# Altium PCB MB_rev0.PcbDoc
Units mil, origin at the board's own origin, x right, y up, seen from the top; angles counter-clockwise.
Board outline 9750 x 2000 mil, 2 copper layers (Top Layer, Bottom Layer); 81 components, 58 nets, 289 pads, 92 vias.
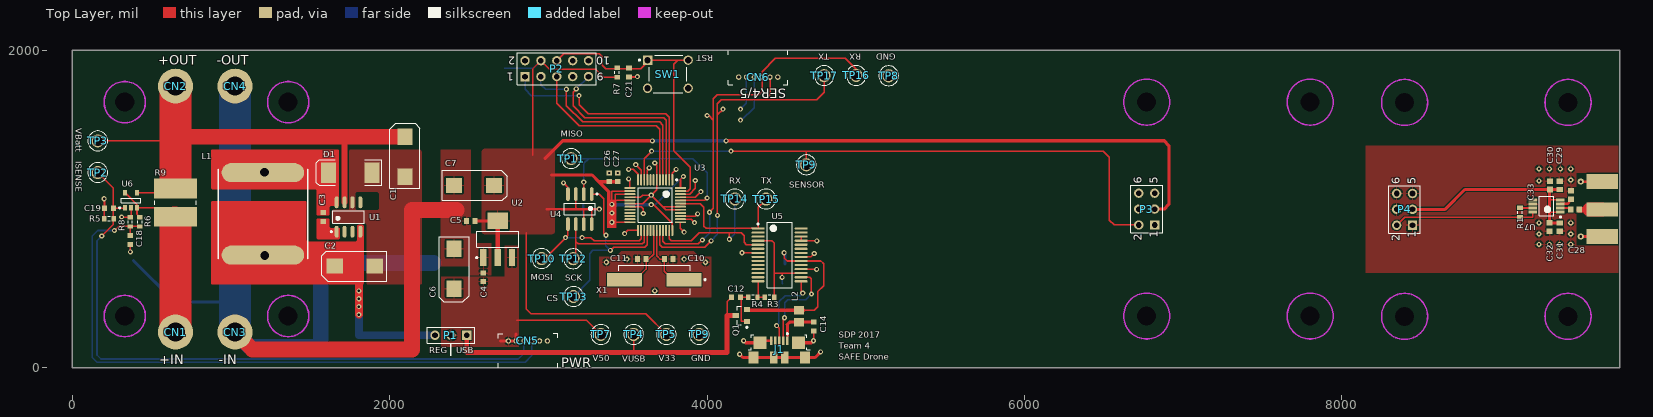
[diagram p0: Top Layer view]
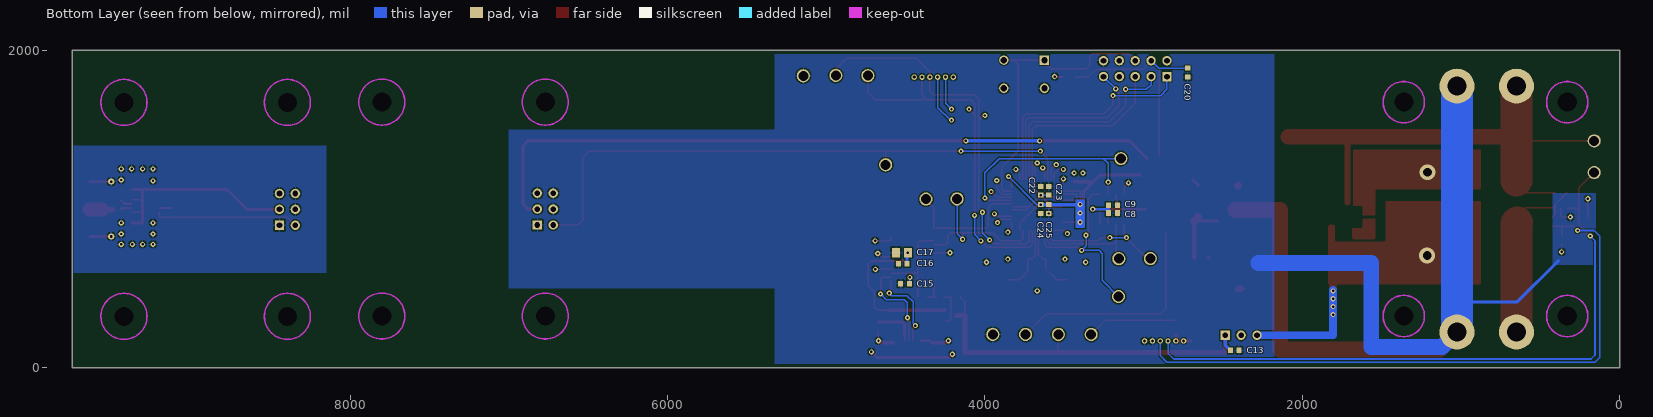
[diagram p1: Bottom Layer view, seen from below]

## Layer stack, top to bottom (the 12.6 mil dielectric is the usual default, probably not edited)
Top Solder: solder mask 0.4, Solder Resist, Dk 3.5
Top Layer: signal copper 1.4
Dielectric 1: dielectric 12.6, FR-4, Dk 4.8
Bottom Layer: signal copper 1.4
Bottom Solder: solder mask 0.4, Solder Resist, Dk 3.5

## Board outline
0,0 9750,0 9750,2000 0,2000

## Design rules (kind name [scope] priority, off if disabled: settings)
Clearance [All] p1: gap=8 ignorepadtopadclearanceinfootprint=TRUE except(0: Arc-Hole Track-Hole SMDPad-Hole THPad-Hole Via-Hole Fill-Hole Poly-Hole Region-Hole Text-Hole; 7: Arc-SMDPad Track-SMDPad SMDPad-SMDPad)
HoleSize [All] p1: absolutevalues=TRUE maxlimit=200 minlimit=15 maxpercent=80.000 minpercent=20.000
MinimumSolderMaskSliver [All] p1: minsoldermaskwidth=2.5
NetAntennae [All] p1 off: netantennaetolerance=20
PolygonConnect PolygonConnect_1 [(InComponent('U1') OR InComponent('C1') OR InComponent('C2') OR InComponent('D1'))] p1: connectstyle=Direct reliefconductorwidth=10 reliefentries=4 polygonreliefangle="90 Angle" airgapwidth=0
PolygonConnect [All] p2: connectstyle=Relief reliefconductorwidth=10 reliefentries=4 polygonreliefangle="90 Angle" airgapwidth=10
RoutingVias [All] p1: holewidth=15 width=32 viastyle="Through Hole" minholewidth=15 minwidth=32 maxholewidth=60 maxwidth=100
SilkToSilkClearance [All] p1 off: silktosilkclearance=6
SilkToSolderMaskClearance [IsPad] p1 off: minsilkscreentomaskgap=10 clearancetoexposedcopper=TRUE
SolderMaskExpansion [All] p1: expansion=4
Width [All] p1: maxlimit=300 minlimit=8 preferedwidth=8 minimp=50.000000 maximp=50.000000 favimp=50.000000
25 further rules are at their usual default settings.

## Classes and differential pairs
component class PSU: C1 C2 C3 C4 C5 C6 C7 C18 C19 CN1 CN2 CN3 CN4 D1 L1 P1 R5 R6 R8 R9 TP2 TP3 TP4 TP5 TP7 TP8 TP9 U1 U2 U6
component class COMS: C12 C13 C14 C15 C16 C17 J1 L2 Q1 R3 R4 RX TP14 TP15 U5
component class MCU: C8 C9 C10 C11 C20 C21 C22 C23 C24 C25 C26 C27 P2 R7 SW1 TP9 TP10 TP11 TP12 TP13 U3 U4 X1
component class WIRE: CN5 CN6 P3 TP16 TP17
component class SENS: C28 C29 C30 C31 C32 C33 P4 R1 U7

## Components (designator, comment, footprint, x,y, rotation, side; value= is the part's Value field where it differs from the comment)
C1 "15uF 25V" AVX-CAPC7343_V 2095,1330 r270 top
C2 "100uF 10V" AVX-CAPC7343_V 1780,640 r0 top
C3 "Cap Semi" 1608[0603] 1580,950 r270 top value=0.01uF
C4 "Cap Semi" 1608[0603] 2590,570 r270 top value=TBD
C5 "Cap Semi" 1608[0603] 2510,925 r0 top value=TBD
C6 "15uF 25V" AVX-CAPC7343_V 2405.28,624.09 r90 top
C7 "15uF 25V" AVX-CAPC7343_V 2530,1150 r180 top
C8 "Cap Semi" 1608[0603] 3192.56,975 r0 bottom value=0.01uF
C9 "Cap Semi" 1608[0603] 3192.56,1025 r180 bottom value=1uF
C10 "Cap Semi" 1608[0603] 3757.56,685 r180 top value=32pF
C11 "Cap Semi" 1608[0603] 3587.56,685 r0 top value=32pF
C12 "Cap Semi" 1608[0603] 4182.56,445 r180 top value=0.1uF
C13 "Cap Semi" 1608[0603] 2425,110 r0 bottom value=0.1uF
C14 "Cap Semi" 1608[0603] 4672.56,260 r90 top value=10nF
C15 "Cap Semi" 1608[0603] 4502.56,530 r0 bottom value=100nF
C16 "Cap Semi" 1608[0603] 4517.56,655 r180 bottom value=100nF
C17 "0805" 2012[0805] 4522.56,725 r180 bottom value=4.7uF
C18 "Cap Semi" 1608[0603] 365,805 r270 top value=100nF
C19 "Cap Semi" 1608[0603] 230,1005 r180 top value=100nF
C20 "Cap Semi" 1608[0603] 2722.56,1860 r90 bottom value=100nF
C21 "Cap Semi" 1608[0603] 3507.56,1860 r90 top value=100nF
C22 "Cap Semi" 1608[0603] 3647.56,1115 r90 bottom value=470pF
C23 "" 1608[0603] 3597.56,1115 r270 bottom value=2.2uF
C24 "Cap Semi" 1608[0603] 3647.56,1000 r270 bottom value=1nF
C25 "" 1608[0603] 3597.56,1000 r90 bottom value=4.7uF
C26 "Cap Semi" 1608[0603] 3382.56,1200 r90 top value=10nF
C27 "Cap Semi" 1608[0603] 3437.56,1200 r90 top value=1uF
C28 "680pF 0603" "CAP 680pF 0603" 9468.43,997 r180 top
C29 "100pF 0603" "Surface mnt capacitor" 9372,1149.38 r90 top
C30 "0.1uF 0603" "Surface mnt Cap" 9312,1149.57 r270 top
C31 "100pF 0603" "Surface mnt capacitor" 9373,886.62 r90 top
C32 "0.1uF 0603" "Surface mnt Cap" 9308,886.43 r90 top
C33 "680pF 0603" "CAP 680pF 0603" 9445,1088 r270 top
CN1 "+IN" WireConn_120mil 650,225 r0 top
CN2 "+OUT" WireConn_120mil 650,1775 r0 top
CN3 "-IN" WireConn_120mil 1025,225 r0 top
CN4 "-OUT" WireConn_120mil 1025,1775 r0 top
CN5 "PWR" CONN_PICOBLADE_6P 2747.15,35.14 r0 top
CN6 "SER4/5" CONN_PICOBLADE_6P 4445,1965 r180 top
D1 "Diode_SMC" SMC 1750,1230 r180 top
J1 "Micro-B USB" HIRO-ZX62R-B-5P_V 4454.09,117.66 r0 top locked
L1 "PE-53823SNL" IND_TOROID_SMT_PULSE 1200,970 r270 top
L2 "Ferrite" INDC2013X105X50ML20T30 4577.56,325 r90 top
P1 "Header 3" HDR1X3 2485,205 r180 top
P2 "JTAG" HDR2X5 2852.56,1835 r0 top
P3 "Header 3X2" HDR2X3 6820,900 r90 top locked
P4 "Header 3X2" HDR2X3 8445,898 r90 top locked
Q1 "IRLML6402G" INTR-SOT-23-3_V 4215,330 r90 top
R1 "Res3" J1-0603 9122,978 r270 top value=0R
R3 "Res3" J1-0603 4392.56,445 r0 top value=1K
R4 "Res3" J1-0603 4287.56,445 r180 top value=1K
R5 "Res3" J1-0603 230,940 r180 top value=49.9k
R6 "Res3" J1-0603 425,920 r270 top value=14k
R7 "Res3" J1-0603 3432.56,1860 r270 top value=10k
R8 "Res3" J1-0603 365,920 r90 top value=1.5k
R9 "CSS2725FTL500CT-ND" STAC-CSS2725-099H_V 650,1040 r90 top
SW1 "B3F-1000" OMRON-B3F-1000-4_V 3752.56,1850 r0 top locked
TP2 "ISENSE" KSTN-5011_V 160,1230 r0 top
TP3 "VBatt" KSTN-5011_V 160,1430 r0 top
TP4 "VUSB" KSTN-5011_V 3536.67,210 r0 top
TP5 "V33" KSTN-5011_V 3743.33,210 r0 top
TP7 "V50" KSTN-5011_V 3330,210 r0 top
TP8 "GND" KSTN-5011_V 5144,1840 r0 top
TP9 "SENSOR" KSTN-5011_V 4625,1279 r0 top
TP9 "GND" KSTN-5011_V 3950,210 r0 top
TP10 "MOSI" KSTN-5011_V 2957,688 r0 top
TP11 "MISO" KSTN-5011_V 3143,1318 r0 top
TP12 "SCK" KSTN-5011_V 3156,687 r0 top
TP13 "CS" KSTN-5011_V 3158,449 r0 top
TP14 "RX" KSTN-5011_V 4175,1064 r0 top
TP15 "TX" KSTN-5011_V 4371,1063 r0 top
TP16 "RX" KSTN-5011_V 4939,1842 r0 top
TP17 "TX" KSTN-5011_V 4737,1841 r0 top
U1 "LM2675MX-5.0" M08A_L 1740,950 r90 top
U2 "LM1117IMPX-3.3" MP04A_M 2680,810 r90 top
U3 "AT32UC3B1256-AUT" TQFP48_N 3672.56,1025 r270 top locked
U4 "8K EEPROM" SOIC-SN8_N 3197.56,1000 r270 top locked
U5 "FT232RL" SSOP-28_N 4456.73,711.34 r0 top locked
U6 "INA169" SOT23-5BL 370,1055 r90 top
U7 "MAX2015" TSOP65P490X110-8N 9026.8,1134.77 r180 top
X1 "ABLS2-32.000MHZ-D4YF-T" ABRA-ABLS2-2_V 3667.56,555 r180 top

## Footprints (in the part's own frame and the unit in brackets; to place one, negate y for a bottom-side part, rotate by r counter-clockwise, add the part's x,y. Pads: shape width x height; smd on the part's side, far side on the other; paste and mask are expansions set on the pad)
1608[0603] [mm] "Chip Capacitor, Body 1.6x0.8mm, IPC High Density"
  rect 0.8x0.9 smd: 1(-0.7,0) 2(0.7,0)
  body extent -0.87,-0.48 0.87,0.48, height 1.3
2012[0805] [mm] "Chip Resistor; Body 2.0 x 1.3 mm (LxW typ)"
  rect 1.3x1.5 smd: 1(-0.95,0) 2(0.95,0)
ABRA-ABLS2-2_V [mm] "SMD, 2-Leads, Body 11.4x4.7mm, Height 3.3mm"
  rect 5.6x2.1 smd: 1(-4.75,0) 2(4.75,0)
  silkscreen extent -8.23,-2.35 5.7,2.35, body extent -5.7,-2.35 5.7,2.35, height 3.3
AVX-CAPC7343_V [mm] "SMT Capacitor, 2 Leads, Body 7.3x4.3mm"
  rect 2.6x2.4 smd: 1(-3.202,0.007) 2(3.198,0.007)
  silkscreen extent -5.33,-2.4 5.08,2.4, body extent -3.49,-2.03 3.51,2.04, height 2.9
"CAP 680pF 0603" [mm] "Chip Capacitor, 2-Leads, Body 1.60x0.80mm, IPC Medium Density"
  rect 0.85x0.95 smd: 1(-0.675,0) 2(0.675,0)
  body extent -0.85,-0.45 0.85,0.45, height 0.9
CONN_PICOBLADE_6P [mm]
  round 0.864 hole 0.5: 1(0,3.4) 2(1.25,3.4) 3(2.5,3.4) 4(3.75,3.4) 5(5,3.4) 6(6.25,3.4)
  silkscreen extent -1.63,-0.86 7.9,4.6, body extent -1.5,-1.05 7.75,4.45, height 3.5
HDR1X3 [mm] "Connector; Header; 3 Position"
  rect 1.5x1.5 hole 0.9: 1(0,0)
  round 1.5 hole 0.9: 2(2.54,0) 3(5.08,0)
  silkscreen extent -1.27,-1.27 6.35,1.27
HDR2X3 [mm] "Connector; Header; 3x2 Position"
  rect 1.5x1.5 hole 0.9: 1(0,0)
  round 1.5 hole 0.9: 2(0,2.54) 3(2.54,0) 4(2.54,2.54) 5(5.08,0) 6(5.08,2.54)
  silkscreen extent -1.27,-1.27 6.35,3.81
HDR2X5 [mm] "Connector; Header; 5x2 Position"
  rect 1.5x1.5 hole 0.9: 1(0,0)
  round 1.5 hole 0.9: 2(0,2.54) 3(2.54,0) 4(2.54,2.54) 5(5.08,0) 6(5.08,2.54) 7(7.62,0) 8(7.62,2.54) 9(10.16,0) 10(10.16,2.54)
  silkscreen extent -1.27,-1.27 11.43,3.81
HIRO-ZX62R-B-5P_V [mm] "USB Micro-B R/A Connector"
  rect 0.4x1.35 smd: 1(1.3,1.338) 2(0.65,1.338) 3(0,1.338) 4(-0.65,1.338) 5(-1.3,1.338)
  rect 2.1x2 smd: 6(-3.1,1.012) 11(3.1,1.012)
  rect 1.6x1.9 smd: 7(-4.1,-1.338) 10(4.1,-1.338)
  rect 1.2x1.9 smd: 8(-0.85,-1.338) 9(0.85,-1.338)
  silkscreen extent -4.95,-0.13 4.95,2.58, body extent -4.4,-3.95 4.4,1.78, height 2.71
IND_TOROID_SMT_PULSE [mil] "LCI-37 PACKAGE"
  oval 120x520 smd: 1(-260,0) 2(260,0)
  silkscreen extent -282,-282 282,282, body extent -285,-285 285,285, height 360
INDC2013X105X50ML20T30 [mm] "Chip Inductor, 2-Leads, Body 2.2x1.45mm, IPC Low Density"
  rect 1.39x1.59 smd: 1(-0.955,0) 2(0.955,0)
  body extent -1.1,-0.72 1.1,0.72, height 1.05
INTR-SOT-23-3_V [mm] "SOT23, 3-Leads, Body 2.92x1.3mm, Pitch 1.9mm"
  rect 0.802x0.972 smd: 1(-0.95,-0.885) 2(0.95,-0.885) 3(0,0.885)
  silkscreen extent -2.03,-1.01 1.46,0.64, body extent -1.46,-0.65 1.46,0.65, height 1.12
J1-0603 [mm] "Chip Resistor, Body 1.6x0.8mm, IPC High Density"
  rect 0.7x0.9 smd: 1(-0.75,0) 2(0.75,0)
  silkscreen extent -0.2,-0.35 0.2,0.35, body extent -0.85,-0.48 0.85,0.48, height 0.9
KSTN-5011_V [mm] "Test Point, Dia 3.17mm"
  round 2.1 hole 1.6: 1(0,0)
  silkscreen extent -1.59,-1.58 1.59,1.58, body extent -1.59,-1.59 1.59,1.59, height 8.13
M08A_L [mm] "SOIC, 8-Leads, Body 4.9x3.9mm, Pitch 1.27mm, IPC High Density"
  oval 1.9x0.6 smd: 1(-2.35,1.905) 2(-2.35,0.635) 3(-2.35,-0.635) 4(-2.35,-1.905) 5(2.35,-1.905) 6(2.35,-0.635) 7(2.35,0.635) 8(2.35,1.905)
  silkscreen extent -2.47,-2.5 1,2.88, body extent -2,-2.5 2,2.5, height 1.75
MP04A_M [mm] "SOT223, 4-Leads, Body 6.5x3.5mm, Pitch 2.3mm, Lead Span 7mm, IPC Low Density"
  rect 2.7x1 smd: 1(-2.95,2.3) 2(-2.95,0) 3(-2.95,-2.3)
  rect 2.7x3.3 smd: 4(2.95,0)
  silkscreen extent -3.07,-3.35 1.3,3.47, body extent -1.86,-3.35 1.86,3.35, height 1.8
OMRON-B3F-1000-4_V [mm] "TH, 4-Leads, Body 6x6mm"
  rect 1.5x1.5 hole 1 paste+0: 1(-3.25,2.25)
  round 1.5 hole 1 paste+0: 2(3.25,2.25) 3(-3.25,-2.25) 4(3.25,-2.25)
  silkscreen extent -4.67,-3 3,3, body extent -3,-3 3,3, height 4.5
SMC [mm] "DO-214-AB/SMC; 2 C-Bend Leads; Body 7.9 x 5.9 mm, inc. leads (LxW)"
  rect 2.4x3.3 smd: 1(-3.475,0) 2(3.475,0)
  silkscreen extent -5.07,-2.05 5.43,2.05
SOIC-SN8_N [mm] "SOIC, 8-Leads, Body 4.9x3.9mm, Pitch 1.27mm, IPC Medium Density"
  oval 2.2x0.6 smd: 1(-2.4,1.905) 2(-2.4,0.635) 3(-2.4,-0.635) 4(-2.4,-1.905) 5(2.4,-1.905) 6(2.4,-0.635) 7(2.4,0.635) 8(2.4,1.905)
  silkscreen extent -2.52,-2.5 0.9,2.88, body extent -2,-2.5 2,2.5, height 1.75
SOT23-5BL [mm] "SOT23, 5-Leads, Body 2.9x1.6mm, Pitch 0.95mm, Lead Span 2.8mm, IPC High Density"
  rect 0.9x0.65 smd: 1(-1.2,0.95) 2(-1.2,0) 3(-1.2,-0.95) 4(1.2,-0.95) 5(1.2,0.95)
  silkscreen extent -1.32,-1.55 0.35,1.95, body extent -0.9,-1.55 0.9,1.55, height 1.19
SSOP-28_N [mm] "SOP, 28-Leads, Body 10.2x5.3mm, Pitch 0.65mm, IPC Medium Density"
  oval 2.1x0.35 smd: 1(-3.45,4.225) 2(-3.45,3.575) 3(-3.45,2.925) 4(-3.45,2.275) 5(-3.45,1.625) 6(-3.45,0.975) 7(-3.45,0.325) 8(-3.45,-0.325) 9(-3.45,-0.975) 10(-3.45,-1.625) 11(-3.45,-2.275) 12(-3.45,-2.925) 13(-3.45,-3.575) 14(-3.45,-4.225) 15(3.45,-4.225) 16(3.45,-3.575) 17(3.45,-2.925) 18(3.45,-2.275) 19(3.45,-1.625) 20(3.45,-0.975) 21(3.45,-0.325) 22(3.45,0.325) 23(3.45,0.975) 24(3.45,1.625) 25(3.45,2.275) 26(3.45,2.925) 27(3.45,3.575) 28(3.45,4.225)
  silkscreen extent -3.57,-5.25 2,5.25, body extent -2.8,-5.25 2.8,5.25, height 2
STAC-CSS2725-099H_V [mm] "Chip Resistor, 2-Leads, Body 7.06x6.7mm"
  rect 3.18x6.86 smd: 1(-2.25,0) 2(2.25,0)
  silkscreen extent -0.3,-3.33 0.3,3.33, body extent -3.53,-3.35 3.53,3.35, height 1.24
"Surface mnt Cap" [mm] "0.1uF 0603"
  rect 0.9x1 smd: 1(-0.675,0) 2(0.675,0)
  body extent -0.87,-0.48 0.87,0.47, height 0.87
"Surface mnt capacitor" [mm] "100pF 0603"
  rect 0.84x1.02 smd: 1(-0.67,0) 2(0.67,0)
  body extent -0.89,-0.51 0.88,0.5, height 0.91
TQFP48_N [mm] "Thin QFP, 48-Leads, Body 7x7mm, Pitch 0.5mm, IPC Medium Density"
  oval 1.8x0.3 smd: 1(-4.05,2.75) 2(-4.05,2.25) 3(-4.05,1.75) 4(-4.05,1.25) 5(-4.05,0.75) 6(-4.05,0.25) 7(-4.05,-0.25) 8(-4.05,-0.75) 9(-4.05,-1.25) 10(-4.05,-1.75) 11(-4.05,-2.25) 12(-4.05,-2.75) 25(4.05,-2.75) 26(4.05,-2.25) 27(4.05,-1.75) 28(4.05,-1.25) 29(4.05,-0.75) 30(4.05,-0.25) 31(4.05,0.25) 32(4.05,0.75) 33(4.05,1.25) 34(4.05,1.75) 35(4.05,2.25) 36(4.05,2.75)
  oval 0.3x1.8 smd: 13(-2.75,-4.05) 14(-2.25,-4.05) 15(-1.75,-4.05) 16(-1.25,-4.05) 17(-0.75,-4.05) 18(-0.25,-4.05) 19(0.25,-4.05) 20(0.75,-4.05) 21(1.25,-4.05) 22(1.75,-4.05) 23(2.25,-4.05) 24(2.75,-4.05) 37(2.75,4.05) 38(2.25,4.05) 39(1.75,4.05) 40(1.25,4.05) 41(0.75,4.05) 42(0.25,4.05) 43(-0.25,4.05) 44(-0.75,4.05) 45(-1.25,4.05) 46(-1.75,4.05) 47(-2.25,4.05) 48(-2.75,4.05)
  silkscreen extent -4.17,-2.75 2.75,3.58, body extent -3.5,-3.5 3.5,3.5, height 1.2
TSOP65P490X110-8N [mm] "TSOP, 8-Leads, Body 3.00x3.00mm, Pitch 0.65mm, IPC Medium Density"
  rect 1.35x0.5 smd: 1(-8.9,3.9) 2(-8.9,3.25) 3(-8.9,2.6) 4(-8.9,1.95) 5(-4.45,1.95) 6(-4.45,2.6) 7(-4.45,3.25) 8(-4.45,3.9)
  silkscreen extent -9.02,1.37 -5.52,4.82, body extent -9.13,1.37 -4.22,4.47, height 1.1
WireConn_120mil [mil]
  round 220 hole 120: 1(0,0)

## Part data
C1 C6 C7: library part CMP-0279-00002-2, "15µF ±10% Molded Tantalum Capacitors 25V 2312 (6032 Metric) 100 mOhm", Capacitance=15uF, Manufacturer=AVX, PartNumber=TPSD156K025S0100, Rated Voltage=25V, Tolerance=10%
C2: library part CMP-0279-00002-2, "15µF ±10% Molded Tantalum Capacitors 10V 2312 (6032 Metric) 50 mOhm", Capacitance=100uF, Manufacturer=AVX, PartNumber=TPSD156K025S0100, Rated Voltage=10V, Tolerance=10%
C3 C4 C5 C8 C9 C10 C11 C12 C13 C14 C15 C16 C18 C19 C20 C21: "Capacitor (Semiconductor SIM Model)"
C17: library part "Cap SMT", "Capacitor (Semiconductor SIM Model)"
C22 C24 C26 C27: "Capacitor (Semiconductor SIM Model)", Tempco=NP0
C23 C25: library part "Cap SMT", "Capacitor (Semiconductor SIM Model)", Tempco=X7R
C28 C33: library part "Surface Mount Cap", "Surface Mount Capacitor"
C29 C31: library part "Surface mnt cap 100pF"
CN1 CN2 CN3 CN4: library part Wire_Conn_Batt
CN5 CN6: library part CONN_PicoBlade_6P_RA, "PicoBlade right angle through hole conn", Insulation Color=Natural, Manufacturer="Molex, LLC", Manufacturer Part Number=0530480610, Supplier Part Number 1=WM1746-ND
D1: "DO-214-AB / SMC SCHOTTKY"
J1: library part CMP-0031-00001-1, "Connector; USBMicro-B,Reverse type, SMT; 5 Position; Right Angle", Operating Temperature="-30 to 85 degC", PartNumber=ZX62R-B-5P(30)
L1: "FIXED IND 38UH 1.2A 100 MOHM SMD", Current - Saturation=-, Current Rating=1.2A, DC Resistance (DCR)="100 mOhm", Inductance=38µH, Manufacturer="Pulse Electronics Corporation", Operating Temperature="-40°C ~ 130°C", Package / Case=Nonstandard, Supplier Part Number 1=33uH
L2: library part CMP-1660-00003-1, "Chip Inductor, 21 Ohm, +/- 30%, 6 A, -40 to 125 degC, 0805 (2012 Metric), RoHS, Tape and Reel", Case\Package=0805, Case Code (Metric)=2012, Current Rating="6 A", Max Operating Temperature="125 degC", Min Operating Temperature="-40 degC", Package Quantity=1, Resistance="4 mohm", Tolerance=30%
P1: "Header, 3-Pin"
P2: library part "Header 5X2", "Header, 5-Pin, Dual row"
P3 P4: "Header, 3-Pin, Dual row"
Q1: library part CMP-0676-00001-1, "HEXFET Power MOSFET, P-Channel, -20 V VDSS, 0.065 Ohm RDS, 3-Pin SOT23, RoHS, Tape and Reel", Manufacturer="International Rectifier", PartNumber=IRLML6402GPbF
R1 R3 R4 R7: "Resistor"
R5 R6 R8: "Resistor", Tempco=25ppm
R9: library part CMP-1719-00001-2, "Chip Resistor, 0.5 mOhm, +/- 1%, 4 W, -55 to 225 degC, 2725 (6865 Metric), RoHS, Tape and Reel", Max Operating Temperature="225 degC", Min Operating Temperature="-55 degC", Package Quantity=1000, Resistance="0.5 mOhm", Tolerance=1%
SW1: library part CMP-1677-00002-1, "Tactile Switch, SPST-NO, 0.05 A, 5 to 24 V, -25 to 70 degC, 4-Pin THD, RoHS, Bulk", Capacitance="-45 f", Current Rating="1.5 A", Max Operating Temperature="70 degC", Min Operating Temperature="-40 degC", Package Quantity=1080, Voltage Rating="150 V"
TP2 TP3 TP4 TP5 TP7 TP8 TP9 TP9 TP10 TP11 TP12 TP13 TP14 TP15 TP16 TP17: library part CMP-1672-00003-4, "Test Point, Black, Through Hole, RoHS, Bulk", Colour=Black, Manufacturer=Keystone, Package Quantity=100
U1: library part CMP-0069-00673-2, "SIMPLE SWITCHER® Power Converter High Efficiency 1A Step-Down Voltage Regulator, 8-pin Narrow SOIC", Manufacturer="National Semiconductor", PackageTopMarking=NSZXTT*2675*M5.0, PowerWise=N
U2: library part CMP-0062-01630-3, "800mA Low-Dropout Linear Regulator, 4-pin SOT-223", Manufacturer="National Semiconductor", PackageTopMarking=XYTT*N05B, PowerWise=N
U3: "32-bit AVR UC3 B Series Microcontroller, 256KB Flash, 32KB SRAM, 28 GPIO pins, Industrial Grade, 48-Pin TQFP, Tray", Supplier Part Number 1=AT32UC3B1256-AUT-ND
U4: library part CMP-0165-00135-1, "8K SPI Bus Serial EEPROM, 8-Pin SOIC, Tape and Reel", Manufacture PN=CAT25080VI-GT3
U5: library part CMP-0078-00028-3, "USB UART Asynchronous Serial Data Transfer Chip, 28-pin SSOP, Tube", Manufacturer=FTDI, PartNumber=FT232RL-Tube
U6: Current - Output=-, Manufacturer="Texas Instruments", Manufacturer Part Number=INA169NA/250, Operating Temperature="-40°C ~ 85°C", Package / Case="SC-74A, SOT-753", Supplier Device Package=SOT-23-5, Voltage - Input="2.7 V ~ 60 V"
U7: "IC"
X1: library part CMP-0277-00002-1, "Low Profile Surface Mount Microprocessor Crystal, 4.096 MHz +/-30 ppm, 180 Ohm, -40 to 85 degC, 2-Pin 11.4 x 4.7 x 3.3 mm SMD, RoHS, Tape and Reel", Freq. Stability="+/- 30 ppm", Frequency="32.0 MHz", Load Capacitance="18 pF", Manufacturer=Abracon, Operating Temp. Range="-40 to 85 degC", Shunt Capacitance="7 pF Max."

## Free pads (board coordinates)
  rect 200x95 smd: 1(9640,827.5) 1(9640,1172.5)
  rect 200x90 smd: 1(9640,997)
  round 0 hole 120: 3(330.1,326) 3(330.1,1674) 3(1360.1,326) 3(1360.1,1674) 3(6770,326) 3(6770,1674) 3(7800,326) 3(7800,1674) 3(8395,324) 3(8395,1672) 3(9425,324) 3(9425,1672)

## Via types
v1: diameter 32, hole 15, Top Layer to Bottom Layer, 88 vias
v2: diameter 38, hole 18, Top Layer to Bottom Layer, 2 vias
v3: diameter 100, hole 55, Top Layer to Bottom Layer, 2 vias

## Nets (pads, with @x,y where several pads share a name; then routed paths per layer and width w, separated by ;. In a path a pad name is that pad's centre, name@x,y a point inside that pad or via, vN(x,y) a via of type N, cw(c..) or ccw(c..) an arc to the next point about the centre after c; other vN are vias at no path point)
AIN_SENSOR: P3.2 TP9.1@4625,1279 U3.10 | length 3781.8
  Top Layer w8: U3.10 3603.66,1318.66 v1(3650,1365) ; v1(4150,1365) 4630,1365 ; TP9.1@4625,1279 4625,1360 4630,1365 ; P3.2 6565,900 6535,930 6535,1325 6495,1365 4630,1365
  Bottom Layer w8: v1(3650,1365) v1(4150,1365)
CS: TP13.1 U3.28 U4.1 | length 1220.4
  Top Layer w8: U4.1 3320,1094.49 3350,1064.49 3350,847.56 v1(3362.56,835) ; v1(3390,740) 3410,760 3607.56,760 3623.35,775.79 U3.28
  Bottom Layer w8: TP13.1 3260,551 3260,720 3280,740 v1(3390,740) 3362.56,767.44 v1(3362.56,835)
DM: U3.39 | length 113.7
  Top Layer w8: U3.39 3926.1,956.1 v1(3940,970)
DP: U3.38 | length 96.9
  Top Layer w8: U3.38 3898.58,936.42 v1(3920,915)
GND: C1.2 C2.2 C4.1 C5.1 C6.2 C7.2 C8.1 C9.2 C10.1 C11.1 C13.1 C14.1 C15.2 C16.1 C17.1 C18.2 C19.2 C20.1 C21.1 C22.2 C23.1 C24.2 C25.1 C26.2 C27.2 C29.2 C30.1 C31.1 C32.1 C33.1 CN3.1 CN4.1 CN5.5 CN5.6 CN6.6 D1.1 J1.5 J1.6 J1.7 J1.8 J1.9 J1.10 J1.11 P2.2 P2.10 P3.1 P3.4 P3.5 P3.6 P4.1 P4.4 P4.5 P4.6 pad.1@9640,827.5 pad.1@9640,1172.5 R5.2 R8.2 SW1.3 SW1.4 TP8.1 TP9.1@3950,210 U1.6 U2.1 U3.1 U3.13 U3.19 U3.37 U4.4 U5.7 U5.18 U5.21 U5.25 U5.26 U6.2 U7.5 U7.6 | length 8755.9
  Top Layer w8: v1(3095,1165) 3122.56,1137.44 U4.4 ; v1(3505,1190) 3513.11,1181.89 U3.13 ; U3.19 3584.84,1015.16 3597.56,1002.44 v1(3597.56,972.44) ; U3.1 3780.83,1225.83 v1(3805,1250) ; U3.37 3832.01,877.99 v1(3855,855)
  Top Layer w10: v1(200,1065) 202.44,1062.56 C19.2 200.47,1003.03 R5.2 ; v1(310,950) 310.47,949.53 R8.2 370,954.53 U6.2 ; v1(365,730) C18.2 ; C21.1 3557.44,1832.44 v1(3560,1835) ; v1(4220,725) 4220.87,724.13 U5.7 ; U5.18 4688.23,621.77 v1(4690,620) ; U5.21 4653.54,698.54 v1(4675,720) ; U5.26 U5.25 4690.91,800.91 v1(4691.81,800) ; v1(4670,170) 4672.56,172.56 C14.1
  Top Layer w15: J1.6 4344.84,170.32 J1.5
  Top Layer w18: v2(9505,827.5) pad.1@9640,827.5 ; v2(9505,1172.5) pad.1@9640,1172.5
  Top Layer w20: v1(4205,85) 4225,65 J1.7 J1.8 J1.9 J1.10 4680,65 v1(4715,100) ; v1(4230,170) 4242.48,157.52 J1.6 ; J1.11 4657.52,157.52 v1(4670,170)
  Top Layer w25: U2.1 U2.1@2590,693.86
  Top Layer w50: C7.2 C7.2@2405,1148.82
  Top Layer w100: CN3.1 1135,115 2140,115 2140,995 2420,995
  Bottom Layer w20: 385,675 645,415 1025,415
  Bottom Layer w100: CN3.1 1120,130 1565,130 1565,660 2275,660
  Bottom Layer w200: CN3.1 1025,415 CN4.1
  other v1: 3670,485 3365,665 3990,665 3495,685 3855,685 9242,778 9307,778 9372,778 9442,778 9242,843 9442,843 9242,913 9442,913 9242,1178 9442,1183 3382.56,1227.56 3437.56,1227.56 9242,1253 9307,1253 9377,1253 9442,1253
MISO: TP11.1 U3.44 U4.2 | length 1462.5
  Top Layer w8: U4.2 v1(3222.56,1170) ; U3.44 3984.53,1054.53 v1(4000,1070)
  Bottom Layer w8: TP11.1 3253,1318 ; v1(3222.56,1170) 3222.56,1287.56 3253,1318 ; v1(4000,1070) 4000,1227.56 3909.56,1318 3253,1318
MOSI: TP10.1 U3.26 U4.5 | length 845.5
  Top Layer w8: TP10.1 2975.56,688 v1(3107.56,820) 3122.56,835 U4.5 ; v1@3212.56,815 v1(3212.56,820) 3267.56,820 3287.56,800 3572.56,800 3583.98,811.42 U3.26
  Bottom Layer w8: v1(3107.56,820) v1(3212.56,820)
NetC3_1: C3.1 D1.2 L1.1 U1.8
  other v3: 1210,1232
NetC3_2: C3.2 U1.1
NetC10_2: C10.2 U3.31 X1.1 | length 440.1
  Top Layer w10: U3.31 3682.4,705.16 3702.56,685 C10.2 3730,607.56 3782.56,555 X1.1
NetC11_2: C11.2 U3.30 X1.2 | length 435.6
  Top Layer w10: X1.2 3547.56,555 3615.12,622.56 C11.2 3632.72,685 3662.72,715 U3.30
NetC12_1: C12.1 Q1.1 R4.2 | length 235.2
  Top Layer w8: C12.1 C12.1@4215,445 ; Q1.1 4215,292.6 C12.1@4215,445 ; R4.2 4248.03,445 C12.1@4215,445
NetC15_1: C15.1 R3.2 U5.4 U5.17 | length 687.6
  Top Layer w8: R3.2 R3.2@4422.56,445.47
  Top Layer w10: U5.4 4407.56,800.91 4422.56,785.91 4422.56,596.18 ; R3.2@4422.56,445.47 4422.56,596.18 ; v1(4472.56,570) 4472.56,596.18 ; U5.17 4472.56,596.18 ; 4422.56,596.18 4472.56,596.18
  Bottom Layer w10: v1(4472.56,570) 4472.56,530 C15.1
NetC16_2: C16.2 C17.2 L2.2 Q1.2 U5.20 | length 1146.9
  Top Layer w10: v1(4485.16,725) 4485.16,692.4 4504.61,672.95 U5.20 4717.05,672.95 4735,655 4735,517.44 4697.56,480 4697.56,385 4675.16,362.6 L2.2
  Top Layer w20: Q1.2 4254.65,362.6 4610,362.6
  Bottom Layer w20: v1(4485.16,725) 4490,720.16 C16.2
NetC18_1: C18.1 CN5.4 R6.2 R8.1 | length 4039.7
  Top Layer w10: v1(265,865) 290.47,890.47 R8.1 ; C18.1 R8.1 ; R6.2 R8.1
  Bottom Layer w10: v1(265,865) 160,865 125,830 125,65 155,35 2853,35 2894.79,76.79 CN5.4
NetC19_1: C19.1 CN5.3 R5.1 TP2.1 U6.1 | length 4103.2
  Top Layer w10: TP2.1 257.56,1132.44 C19.1 ; v1(185,830) 257.56,902.56 C19.1 ; U6.1 329.84,1005 C19.1
  Bottom Layer w10: v1(185,830) 155,800 155,80 180,55 2810,55 2845.57,90.57 CN5.3
NetC28_2: C28.2 U7.2 | length 74.5
  Top Layer w15: U7.2 9441.85,1006.82 C28.2
NetC33_2: C33.2 U7.3 | length 72.8
  Top Layer w15: U7.3 9422.26,1032.41 C33.2@9441.85,1052
NetCN1_1: CN1.1 R6.1 R9.1 U6.3 U6.5 | length 1183.3
  Top Layer w10: U6.5 407.4,1027.44 U6.3 ; R6.1 407.4,967.13 U6.3 ; R9.1@645,915 645,956.42 593.66,1007.76 U6.3
  Top Layer w200: R9.1@645,915 650,910 CN1.1
NetCN6_4: CN6.4 | length 310.7
  Bottom Layer w8: v1(4210,1560) 4215.79,1560 4295.79,1640 4295.79,1829.57 CN6.4
NetCN6_5: CN6.5 | length 216.9
  Bottom Layer w8: v1(4210,1630) 4246.57,1666.57 4246.57,1829.57 CN6.5
NetJ1_2: J1.2 U5.16 | length 600.1
  Top Layer w8: J1.2 4479.69,307.13 v1(4487.56,315) ; U5.16 4646.97,570.59 4657.56,560 v1(4657.56,465)
  Bottom Layer w8: v1(4487.56,315) 4487.56,410 4507.56,430 4622.56,430 v1(4657.56,465)
NetJ1_3: J1.3 U5.15 | length 509.7
  Top Layer w8: v1(4437.56,265) 4454.09,248.46 J1.3 ; U5.15 4592.56,480 v1(4602.56,470)
  Bottom Layer w8: v1(4437.56,265) 4452.56,280 4452.56,415 4492.56,455 4587.56,455 v1(4602.56,470)
NetR1_1: R1.1 U7.7 | length 80.3
  Top Layer w10: R1.1 9122.71,1006.82 U7.7
OUT: P4.2 R1.2 U7.8 | length 910.7
  Top Layer w10: P4.2 8395.48,948.48 9066.99,948.48 ; 9066.99,948.47 R1.2 9202,948.47 U7.8
PA03: U3.7
PA04: U3.8
PA05: U3.9 | length 80.4
  Top Layer w8: U3.9 3623.35,1243.35 3635,1255 v1(3635,1260)
PA07: U3.11 | length 109.6
  Top Layer w8: v1(3550,1280) 3583.98,1246.02 U3.11
PA08: U3.12 | length 107.7
  Top Layer w8: v1(3505,1250) 3535,1250 3564.29,1220.71 U3.12
PA09: U3.20
PA10: U3.21
PA11: U3.22
PA12: U3.23
PA13: U3.25 | length 92.8
  Top Layer w8: v1(3480,845) 3500,865 3563.74,865 U3.25
PA17: U3.29
PA22: U3.34
PA26: U3.45 | length 142.8
  Top Layer w8: U3.45 3924.21,1074.21 v1(3960,1110)
PA27: U3.46 | length 157.9
  Top Layer w8: U3.46 3888.9,1093.9 3925,1130 v1(3925,1180)
PWREN: R3.1 R4.1 U5.14 | length 161.7
  Top Layer w8: U5.14 4320.91,458.82 4307.09,445 R3.1
R\S\T\: C21.2 P2.6 R7.1 SW1.1 SW1.2 U3.47 | length 1877.3
  Top Layer w8: P2.6 3097.56,1980 3320,1980 3340,1960 3340,1905 3360,1885 3582.56,1885 3624.61,1927.05 SW1.1 3815,1938.58 ; U3.47 3878.58,1113.58 3892.56,1127.56 3892.56,1265 3790,1367.56 3790,1913.58 3815,1938.58 ; SW1.2 3815,1938.58
RF_IN: C28.1 pad.1@9640,997 | length 145
  Top Layer w35: C28.1 pad.1@9560,997
  Top Layer w90: pad.1@9560,997 pad.1@9640,997
RXD1: TP15.1 U3.43 U5.1 | length 828.8
  Top Layer w8: U3.43 3955.16,1034.84 3980,1010 3980,892.68 3995,877.68 U5.1 4320.91,1012.91 TP15.1
RXD2: CN6.2 TP17.1 U3.32 | length 2329.1
  Top Layer w8: U3.32 3702.09,775.47 3717.56,760 3985,760 v1(4025,800) ; v1(4065,960) 4065,1595 ; v1(4100,1630) 4065,1595 ; CN6.2 4394.21,1829.57 4397,1826.78 4397,1722 4365,1690 ; TP17.1 4737,1737 4690,1690 4365,1690 ; 4065,1595 4065,1665 4090,1690 4365,1690
  Bottom Layer w8: v1(4025,800) 4065,840 v1(4065,960)
SCK: TP12.1 U3.27 U4.6 | length 741.7
  Top Layer w8: TP12.1 3172.56,703.56 3172.56,795 ; U4.6 3172.56,795 ; U3.27 3603.66,791.1 3592.56,780 3187.56,780 3172.56,795
TCK: P2.1 U3.2 | length 1489.7
  Top Layer w8: v1(3192.56,1715) 3192.56,1657.44 3250,1600 3740,1600 3761.14,1578.86 U3.2
  Bottom Layer w8: P2.1 2852.56,1755 2892.56,1715 v1(3192.56,1715)
TDI: P2.9 U3.3 | length 1223.8
  Top Layer w8: v1(3175.06,1757.5) 3155,1737.44 3155,1650 3230,1575 3725,1575 3741.46,1558.54 U3.3
  Bottom Layer w8: v1(3175.06,1757.5) P2.9
TDO: P2.3 U3.4 | length 1329.4
  Top Layer w8: v1(3112.56,1755) 3112.56,1652.44 3215,1550 3700,1550 3721.77,1528.23 U3.4
  Bottom Layer w8: P2.3 2952.56,1785 2982.56,1755 v1(3112.56,1755)
TMS: P2.5 U3.5 | length 1217.2
  Top Layer w8: P2.5@3062.09,1825.47 P2.5 3052.56,1667.44 3195,1525 3680,1525 3702.09,1502.91 U3.5
TXD1: TP14.1 U3.35 U5.5 | length 1003.6
  Top Layer w8: U3.35 3761.14,811.42 3772.56,800 3900,800 3950,850 4140,850 ; v1(4140,810) 4140,850 ; U5.5 4247.24,775.32 4232.56,790 4232.56,832.44 4215,850 4140,850
  Bottom Layer w8: v1(4140,810) 4175,845 TP14.1
TXD2: CN6.3 TP16.1 U3.33 | length 2452.3
  Top Layer w8: U3.33 3721.77,795.79 3737.56,780 3945,780 v1(3970,805) ; v1(4000,1590) 4010,1590 4040,1560 ; v1(4015,980) 4040,1005 4040,1560 ; TP16.1 4939,1882 4871,1950 4430,1950 4346.57,1866.57 CN6.3 4346.57,1741.57 4325,1720 4065,1720 4040,1695 4040,1560
  Bottom Layer w8: v1(3970,805) 4015,850 v1(4015,980)
V18: C22.1 C23.2 U3.6 U3.16 U3.18 U3.41 U3.42 | length 903
  Top Layer w8: U3.18 3594.96,1034.84 v1(3647.56,1087.44) ; U3.16 3580,1074.21 3593.23,1087.44 v1(3647.56,1087.44) ; v1(3670,1290) 3682.4,1277.6 U3.6 3682.4,1122.28 v1(3647.56,1087.44) ; U3.41 3739.53,995.47 3719.84,1015.16 ; U3.42 3719.84,1015.16 ; v1(3647.56,1087.44) 3719.84,1015.16
  Bottom Layer w8: C23.2 v1(3647.56,1087.44)
V33: C5.2 C7.1 C8.2 C9.1 C20.2 C24.1 C25.2 C26.1 C27.1 C29.1 C30.2 C31.2 C32.2 P2.4 P3.3 P4.3 R7.2 TP5.1 U2.2 U2.4 U3.14 U3.15 U3.17 U3.24 U3.36 U3.48 U4.3 U4.7 U4.8 U7.1 U7.4 | length 11892.7
  Top Layer w8: U4.3 3172.56,1007.44 3180,1000 ; 3220,1000 3222.56,997.44 U4.7 ; 3270,1000 3272.56,997.44 U4.8 ; v1(3400,916.73) U3.24 ; 3400,1055 3400,1113.58 U3.14 ; U3.17 3420,1054.53 3420,1093.9 U3.15 ; v1(3647.56,1027.56) 3662.37,1027.56 3780.83,909.1 U3.36
  Top Layer w10: 2860,850 2860,370 2890,340 3613.33,340 TP5.1 ; 2900,1340 2900,1882.44 P2.4 3007.56,1880 3300,1880 3349.53,1830.47 R7.2 ; U3.48 3832.01,1187.01 v1(3850,1205) ; 9308,979 9308,981.23 U7.1 ; 9308,1057 9308,1058 U7.4
  Top Layer w15: 2990,1000 3180,1000 3220,1000 3270,1000 v1(3320,1000)
  Top Layer w20: C5.2 U2.4@2680,925 ; C7.1 C7.1@2691.34,1185 ; 2980,1320 3090,1430 v1(3655,1430) ; 3020,1215 3275,1215 3317.56,1172.44 ; 3410,1000 3380,1030 3380,1110 3317.56,1172.44 ; C27.1 C26.1 3317.56,1172.44 ; v1(4120,1430) 6880,1430 6910,1400 6910,1030 6880,1000 P3.3 ; P4.3 8650,998 8775,1123 C30.2@9308,1123 ; 9308,979 C32.2 C31.2 ; 9308,981.23 9308,1057 ; 9308,1058 C30.2@9308,1123 ; C29.1 C30.2 C30.2@9308,1123
  Top Layer w30: U2.2 U2.4@2680,925
  Top Layer w50: U2.4@2656.06,948.94 U2.4@2680,925
  Bottom Layer w8: C20.2 2905.12,1887.56 P2.4
  Bottom Layer w10: v1(3647.56,1027.56) 3672.56,1027.56 v1(3850,1205)
  Bottom Layer w15: C8.2 3220.12,1000 ; C9.1 3220.12,1000 ; v1(3320,1000) 3220.12,1000
  Bottom Layer w20: v1@3390,1027.56 C25.2 v1(3647.56,1027.56) ; v1(3655,1430) v1(4120,1430)
  other v1: 3400,975 3400,1030
V50: C4.2 C6.1 CN5.1 CN5.2 P1.2 TP7.1 U2.3 | length 728.6
  Top Layer w10: 2800,300 3240,300 TP7.1
  Top Layer w20: 2697,169 CN5.1 CN5.2 2796.36,211
  Top Layer w40: C6.1@2385,498.03 C6.1
VBatt: C1.1 CN2.1 R9.2 TP3.1 U1.7 U6.4 | length 3266.1
  Top Layer w10: TP3.1 630,1430 650,1410 ; U6.4 623.66,1102.24 645,1123.58 R9.2@645,1175
  Top Layer w40: U1.7 1715,1456.06
  Top Layer w100: 650,1495 ccw(c690,1495) 690,1455 cw(c691.06,1455) 691.06,1456.06 1715,1456.06 C1.1@2088,1456.06
  Top Layer w200: R9.2@650,1180 650,1410 650,1495 CN2.1
VBUS: C14.2 J1.1 L2.1 | length 276
  Top Layer w10: J1.1 4505.28,200 ; C14.2@4672.4,287.4 C14.2
  Top Layer w20: 4505.56,200 4505.56,272.43 4505.28,272.72 4519.96,287.4 L2.1 C14.2@4672.4,287.4
Vreg50: C2.1 L1.2 P1.3 U1.4 | length 1005
  Top Layer w50: v1(1805,335) v1(1805,385) v1(1805,435) v1(1805,485) 1805,575
  Bottom Layer w50: v1@1805,490 v1(1805,485) v1(1805,435) v1(1805,385) v1(1805,335) 1805,205 P1.3
  other v3: 1213,707
VUSB: C12.2 C13.2 P1.1 Q1.3 TP4.1 | length 2388.7
  Top Layer w10: TP4.1 3536.67,108.33 3540,105 ; 4125,330 4127.44,332.44 4127.44,417.44 C12.2 ; Q1.3 Q1.3@4187.44,322.72
  Top Layer w30: P1.1 2485,97 4125,97 4125,330 Q1.3
  Bottom Layer w20: C13.2 2485,142.44 P1.1
pads on no net: CN6.1 J1.4 P2.7 P2.8 U1.2 U1.3 U1.5 U3.40 U5.2 U5.3 U5.6 U5.8 U5.9 U5.10 U5.11 U5.12 U5.13 U5.19 U5.22 U5.23 U5.24 U5.27 U5.28

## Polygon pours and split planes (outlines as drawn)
V50 on Top Layer "V50" (solid, pour order 6): 2325,575 2725,575 2725,770 2814,770 2814,132 2325,132
V33 on Top Layer "Top Layer-No Net 1" (solid, pour order 10): 2580,1360 cw(c2600,1360) 2600,1380 3020,1380 cw(c3020,1360) 3040,1360 3040,860 cw(c3020,860) 3020,840 2600,840 cw(c2600,860) 2580,860
GND on Top Layer "Top Layer-No Net" (solid, pour order 4): 3320,445 3320,700 3425,700 3460,735 3915,735 3950,700 4025,700 4025,445
GND on Top Layer "Top Layer-No Net" (solid, pour order 2): 1635,985 cw(c1645,985) 1645,995 1735,995 ccw(c1735,1005) 1745,1005 1745,1365 cw(c1755,1365) 1755,1375 2185,1375 cw(c2185,1360) 2200,1360 2200,535 cw(c2192.48,532.51) 2195,525 1865,525 cw(c1865,535) 1855,535 1855,900 ccw(c1845,900) 1845,910 1645,910 cw(c1645,920) 1635,920
GND on Top Layer "Top Layer-No Net" (solid, pour order 8): 2505,640.71 2505,584 2640,584 2640,785 2545,785 2545,845 2510,845 2510,1375 2320,1375 2320,640.71
GND on Top Layer "Top Layer-No Net 1" (solid, remove dead copper, pour order 22): 8150.67,1400.04 8150.67,600.04 9740.67,600.04 9740.67,1400.04
GND on Bottom Layer "Top Layer-No Net 1" (solid, pour order 28): 2175,1975 5325,1975 5325,1500 7000,1500 7000,500 5325,500 5325,25 2175,25
GND on Bottom Layer "Top Layer-No Net 1" (solid, pour order 16): 150,1100 150,650 420,650 420,1100
GND on Bottom Layer "Top Layer-No Net 1" (solid, remove dead copper, pour order 30): 8150.67,1400.04 8150.67,600.04 9740.67,600.04 9740.67,1400.04

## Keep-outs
Keep-Out Layer:
  circle w10: c330.1,1674 r130
  circle w10: c1360.1,1674 r130
  circle w10: c330.1,326 r130
  circle w10: c1360.1,326 r130
  circle w10: c6770,1674 r145
  circle w10: c7800,1674 r145
  circle w10: c7800,326 r145
  circle w10: c6770,326 r145
  circle w10: c8395,324 r145
  circle w10: c9425,324 r145
  circle w10: c9425,1672 r145
  circle w10: c8395,1672 r145

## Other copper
Top Layer:
  rectangle net V33: 3370,880 3430,1060
  pour cut-out: 9476,1230 9476,770 9750,770 9750,1230
  region net NetC3_1: 875,1365 cw(c885,1365) 885,1375 1670,1375 cw(c1670,1365) 1680,1365 1680,1020 1630,1020 ccw(c1630,1010) 1620,1010 1620,970 cw(c1610,970) 1610,960 1550,960 cw(c1550,970) 1540,970 1540,1115 ccw(c1530,1115) 1530,1125 885,1125 cw(c885,1135) 875,1135
  region net Vreg50: 875,1040 cw(c885,1040) 885,1050 1465,1050 cw(c1465,1040) 1475,1040 1475,805 ccw(c1485,805) 1485,795 1780,795 ccw(c1782.5,807.5) 1795,805 1795,890 cw(c1805,890) 1805,900 1825,900 cw(c1825,890.01) 1835,890 1835,610 1835,592.94 1835,535 cw(c1825.79,534.21) 1825,525 1560,525 1450,525 885,525 cw(c885,535) 875,535
  region net NetC3_2: 1540,930 cw(c1550,930) 1550,940 1610,940 cw(c1610,930) 1620,930 1620,890 ccw(c1630,890) 1630,880 1685,880 1685,820 cw(c1675,820) 1675,810 1550,810 cw(c1550,820) 1540,820
  pour cut-out: 1796.84,995 cw(c1796.84,1005) 1786.84,1005 1786.84,1096.84 cw(c1795,1096.84) 1795,1105 1920,1105 cw(c1920,1095) 1930,1095 1930,1005 cw(c1920,1005) 1920,995
Bottom Layer:
  rectangle net V33: 3370,880 3430,1060

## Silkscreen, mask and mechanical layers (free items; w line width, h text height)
Top Overlay:
  lines w8: 2385,75 2385,155
  text "RST" at 4040,1970 h38 r180
  text "SDP 2017" at 4830,190 h38
  text "Team 4" at 4830,120 h38
  text "REG" at 2250,90 h38
  text "USB" at 2420,90 h38
  text "SAFE Drone" at 4830,50 h38
M1-Board Outline:
  lines w10: 0,0 0,2000 2400,2000 8125,2000 9750,2000 9750,0 8125,0 0,0
M3-PCB Notes for Self:
  circle w10: c330.1,328 r110
  circle w10: c1360.1,328 r110
  circle w10: c1360.1,1676 r110
  circle w10: c330.1,1676 r110
  circle w10: c6770,1672 r110
  circle w10: c7800,1672 r110
  circle w10: c7800,324 r110
  circle w10: c6770,324 r110
  circle w10: c8395,1672 r110
  circle w10: c9425,1672 r110
  circle w10: c9425,324 r110
  circle w10: c8395,324 r110
  lines w10: 1625,0 ccw(c-2310,1000) 1625,2000 ; 1675,2650 1675,3025 ; 1750,2775 1675,2850 ; 1750,2925 1675,2850 ; 2050,-925 1975,-850 ; 2050,-775 1975,-850 ; 2176.13,1999.59 ccw(c4916.5,1000.5) 2176.51,0.38 ; 3125,2850 1675,2850 ; 3425,-850 1975,-850 ; 4825,-850 6100,-850 ; 5225,2850 6500,2850 ; 5948.49,1999.62 cw(c3208.5,999.5) 5948.87,0.41 ; 6025,-925 6100,-850 ; 6025,-775 6100,-850 ; 6425,2775 6500,2850 ; 6425,2925 6500,2850 ; 6500,0 cw(c10435,1000) 6500,2000 ; 6500,2650 6500,3025 ; 7798,1595.1 7798.1,1595 ; 332,1753 ccw(c332,1676) 332.1,1599 1358.21,1599 ; 332,1753 332,1753 ; 332,1753 1358.1,1753 cw(c1358.21,1676) 1358.21,1599 ; 332.1,405 ccw(c332.1,328) 332.21,251 1358.31,251 ccw(c1358.31,328) 1358.21,405 332.1,405 ; 332.1,405 332.1,405 ; 1358.21,1599 1358.21,1599 ; 6771.9,1749 ccw(c6771.9,1672) 6772,1595 7798.1,1595 ; 6771.9,1749 6771.9,1749 ; 6771.9,1749 7798,1749 cw(c7798.1,1672) 7798.1,1595 ; 6772,401 ccw(c6772,324) 6772.1,247 7798.21,247 ; 6772,401 7798.1,401 cw(c7798.21,324) 7798.21,247 ; 6772,401 6772,401 ; 7798.21,247 7798.21,247 ; -40,3240 1960,3240 1960,3440 -40,3440 -40,3240 ; 0,75 75,0 8050,0 8125,75 8125,1925 8050,2000 75,2000 0,1925 0,75 ; 1353.1,251 1353.1,251 ; 8125,0 8125,2000 9750,2000 9750,0 8125,0
  text "NOT FOR FAB - MECH NOTES" at 0,3300 h80
  text "Region between top/bot boards" at 3325,2825 h60
  text "(POWER OUT TO FC)" at 2700,2200 h80
  text "(BATT EXIT)" at 450,2150 h80
  text "SUGG. DAUGHTERBOARD / SIZE: 1.625Wx2.000H" at 8150,2100 h80
  text "Hex standoff (0.290dia OD) x4 / #4-40 screw (0.220dia head) x4" at 9805,1580 h60
  text "Slots in bottom board" at 260,1040 h60
  text "Panhead / #4-40 (x8)" at 110,470 h60
  text "(CURR SENSING)" at 550,-450 h80
  text "(POWER SUPPLIES)" at 1700,-450 h80
  text "MICROCONTROLLER" at 3500,-450 h80
  text "(SERIAL TO FC)" at 3000,-600 h80
  text "(EEPROM?)" at 4400,-600 h80
  text "(BATT ENTER)" at 325,-625 h80
  text "HIGH DC CURRENT REGION" at 3475,-880 h60
Drill Drawing:
  circle w10: c105.62,3400.83 r33.33
  lines w10: 72.29,2467.5 105.62,2484.17 138.96,2467.5 122.29,2500.83 138.96,2534.17 105.62,2517.5 72.29,2534.17 88.96,2500.83 72.29,2467.5 ; 72.29,2684.17 138.96,2684.17 105.62,2617.5 72.29,2684.17 ; 72.29,2767.5 138.96,2767.5 138.96,2834.17 72.29,2834.17 72.29,2767.5 ; 72.29,2934.17 88.96,2934.17 88.96,2917.5 122.29,2917.5 122.29,2934.17 138.96,2934.17 138.96,2967.5 122.29,2967.5 122.29,2984.17 88.96,2984.17 88.96,2967.5 72.29,2967.5 72.29,2934.17 ; 72.29,3134.17 138.96,3134.17 105.62,3067.5 72.29,3134.17 ; 72.29,3234.17 88.96,3234.17 105.62,3217.5 122.29,3234.17 138.96,3234.17 122.29,3250.83 138.96,3267.5 122.29,3267.5 105.62,3284.17 88.96,3267.5 72.29,3267.5 88.96,3250.83 72.29,3234.17 ; 72.29,3517.5 138.96,3517.5 138.96,3584.17 72.29,3584.17 72.29,3517.5 ; 85.62,2670.83 125.62,2670.83 105.62,2630.83 85.62,2670.83 ; 85.62,3530.83 125.62,3530.83 125.62,3570.83 85.62,3570.83 85.62,3530.83
  lines w15: 12.5,2422.5 10593.57,2422.5 ; 12.5,3622.5 10593.57,3622.5 ; 563.38,2272.5 563.38,3772.5 ; 1153.22,2272.5 1153.22,3772.5 ; 2302.88,2272.5 2302.88,3772.5 ; 2808.76,2272.5 2808.76,3772.5 ; 3542.56,2272.5 3542.56,3772.5 ; 5042.11,2272.5 5042.11,3772.5 ; 5631.96,2272.5 5631.96,3772.5 ; 6377.76,2272.5 6377.76,3772.5 ; 7027.59,2272.5 7027.59,3772.5 ; 7881.35,2272.5 7881.35,3772.5 ; 9214.96,2272.5 9214.96,3772.5 ; 12.5,2272.5 10593.57,2272.5 10593.57,3772.5 12.5,3772.5 12.5,2272.5
  text "Symbol" at 102.5,3667.5 h72
  text "Count" at 608.38,3667.5 h72
  text "Hole Size" at 1198.22,3667.5 h72
  text "Plated" at 2347.88,3667.5 h72
  text "Hole Type" at 2853.76,3667.5 h72
  text "Drill Layer Pair" at 3587.56,3667.5 h72
  text "Via/Pad" at 5087.11,3667.5 h72
  text "Pad Shape" at 5676.96,3667.5 h72
  text "Template" at 6422.76,3667.5 h72
  text "Description" at 7072.59,3667.5 h72
  text "Hole Tolerance (+)" at 7926.35,3667.5 h72
  text "Hole Tolerance (-)" at 9259.96,3667.5 h72
  text "2" at 608.38,3517.5 h60
  text "18.00mil (0.457mm)" at 1198.22,3517.5 h60
  text "PTH" at 2347.88,3517.5 h60
  text "Round" at 2853.76,3517.5 h60
  text "Top Layer - Bottom Layer" at 3587.56,3517.5 h60
  text "Via" at 5087.11,3517.5 h60
  text "Rounded" at 5676.96,3517.5 h60
  text "v97h46" at 6422.76,3517.5 h60
  text "2" at 608.38,3367.5 h60
  text "55.00mil (1.397mm)" at 1198.22,3367.5 h60
  text "PTH" at 2347.88,3367.5 h60
  text "Round" at 2853.76,3367.5 h60
  text "Top Layer - Bottom Layer" at 3587.56,3367.5 h60
  text "Via" at 5087.11,3367.5 h60
  text "Rounded" at 5676.96,3367.5 h60
  text "v254h140" at 6422.76,3367.5 h60
  text "4" at 608.38,3217.5 h60
  text "39.37mil (1.000mm)" at 1198.22,3217.5 h60
  text "PTH" at 2347.88,3217.5 h60
  text "Round" at 2853.76,3217.5 h60
  text "Top Layer - Bottom Layer" at 3587.56,3217.5 h60
  text "Pad" at 5087.11,3217.5 h60
  text "(Mixed)" at 5676.96,3217.5 h60
  text "(Mixed)" at 6422.76,3217.5 h60
  text "12" at 608.38,3067.5 h60
  text "19.69mil (0.500mm)" at 1198.22,3067.5 h60
  text "PTH" at 2347.88,3067.5 h60
  text "Round" at 2853.76,3067.5 h60
  text "Top Layer - Bottom Layer" at 3587.56,3067.5 h60
  text "Pad" at 5087.11,3067.5 h60
  text "Rounded" at 5676.96,3067.5 h60
  text "c86h50" at 6422.76,3067.5 h60
  text "16" at 608.38,2917.5 h60
  text "62.99mil (1.600mm)" at 1198.22,2917.5 h60
  text "PTH" at 2347.88,2917.5 h60
  text "Round" at 2853.76,2917.5 h60
  text "Top Layer - Bottom Layer" at 3587.56,2917.5 h60
  text "Pad" at 5087.11,2917.5 h60
  text "Rounded" at 5676.96,2917.5 h60
  text "c210h160" at 6422.76,2917.5 h60
  text "16" at 608.38,2767.5 h60
  text "120.00mil (3.048mm)" at 1198.22,2767.5 h60
  text "PTH" at 2347.88,2767.5 h60
  text "Round" at 2853.76,2767.5 h60
  text "Top Layer - Bottom Layer" at 3587.56,2767.5 h60
  text "Pad" at 5087.11,2767.5 h60
  text "Rounded" at 5676.96,2767.5 h60
  text "(Mixed)" at 6422.76,2767.5 h60
  text "25" at 608.38,2617.5 h60
  text "35.43mil (0.900mm)" at 1198.22,2617.5 h60
  text "PTH" at 2347.88,2617.5 h60
  text "Round" at 2853.76,2617.5 h60
  text "Top Layer - Bottom Layer" at 3587.56,2617.5 h60
  text "Pad" at 5087.11,2617.5 h60
  text "(Mixed)" at 5676.96,2617.5 h60
  text "(Mixed)" at 6422.76,2617.5 h60
  text "88" at 608.38,2467.5 h60
  text "15.00mil (0.381mm)" at 1198.22,2467.5 h60
  text "PTH" at 2347.88,2467.5 h60
  text "Round" at 2853.76,2467.5 h60
  text "Top Layer - Bottom Layer" at 3587.56,2467.5 h60
  text "Via" at 5087.11,2467.5 h60
  text "Rounded" at 5676.96,2467.5 h60
  text "v81h38" at 6422.76,2467.5 h60
  text "165 Total" at 608.38,2317.5 h60

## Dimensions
0,2000 to 0,0 on M3-PCB Notes for Self
0,0 to 8125,0 on M3-PCB Notes for Self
